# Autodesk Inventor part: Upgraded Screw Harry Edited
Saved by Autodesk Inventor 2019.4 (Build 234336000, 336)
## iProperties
Created: 2020-06
Part Number: Upgraded Screw Harry Edited
Material: Generic
Document SubType Name: Modeling
Designer: Administrator
Density: 1 g/cm^3
Appearance: Default
Title: Upgraded Screw Harry Edited v15
Author: Administrator
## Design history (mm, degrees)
feature "Main Body"
body "Solid1"
